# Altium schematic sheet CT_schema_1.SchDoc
size 512 x 258 mm
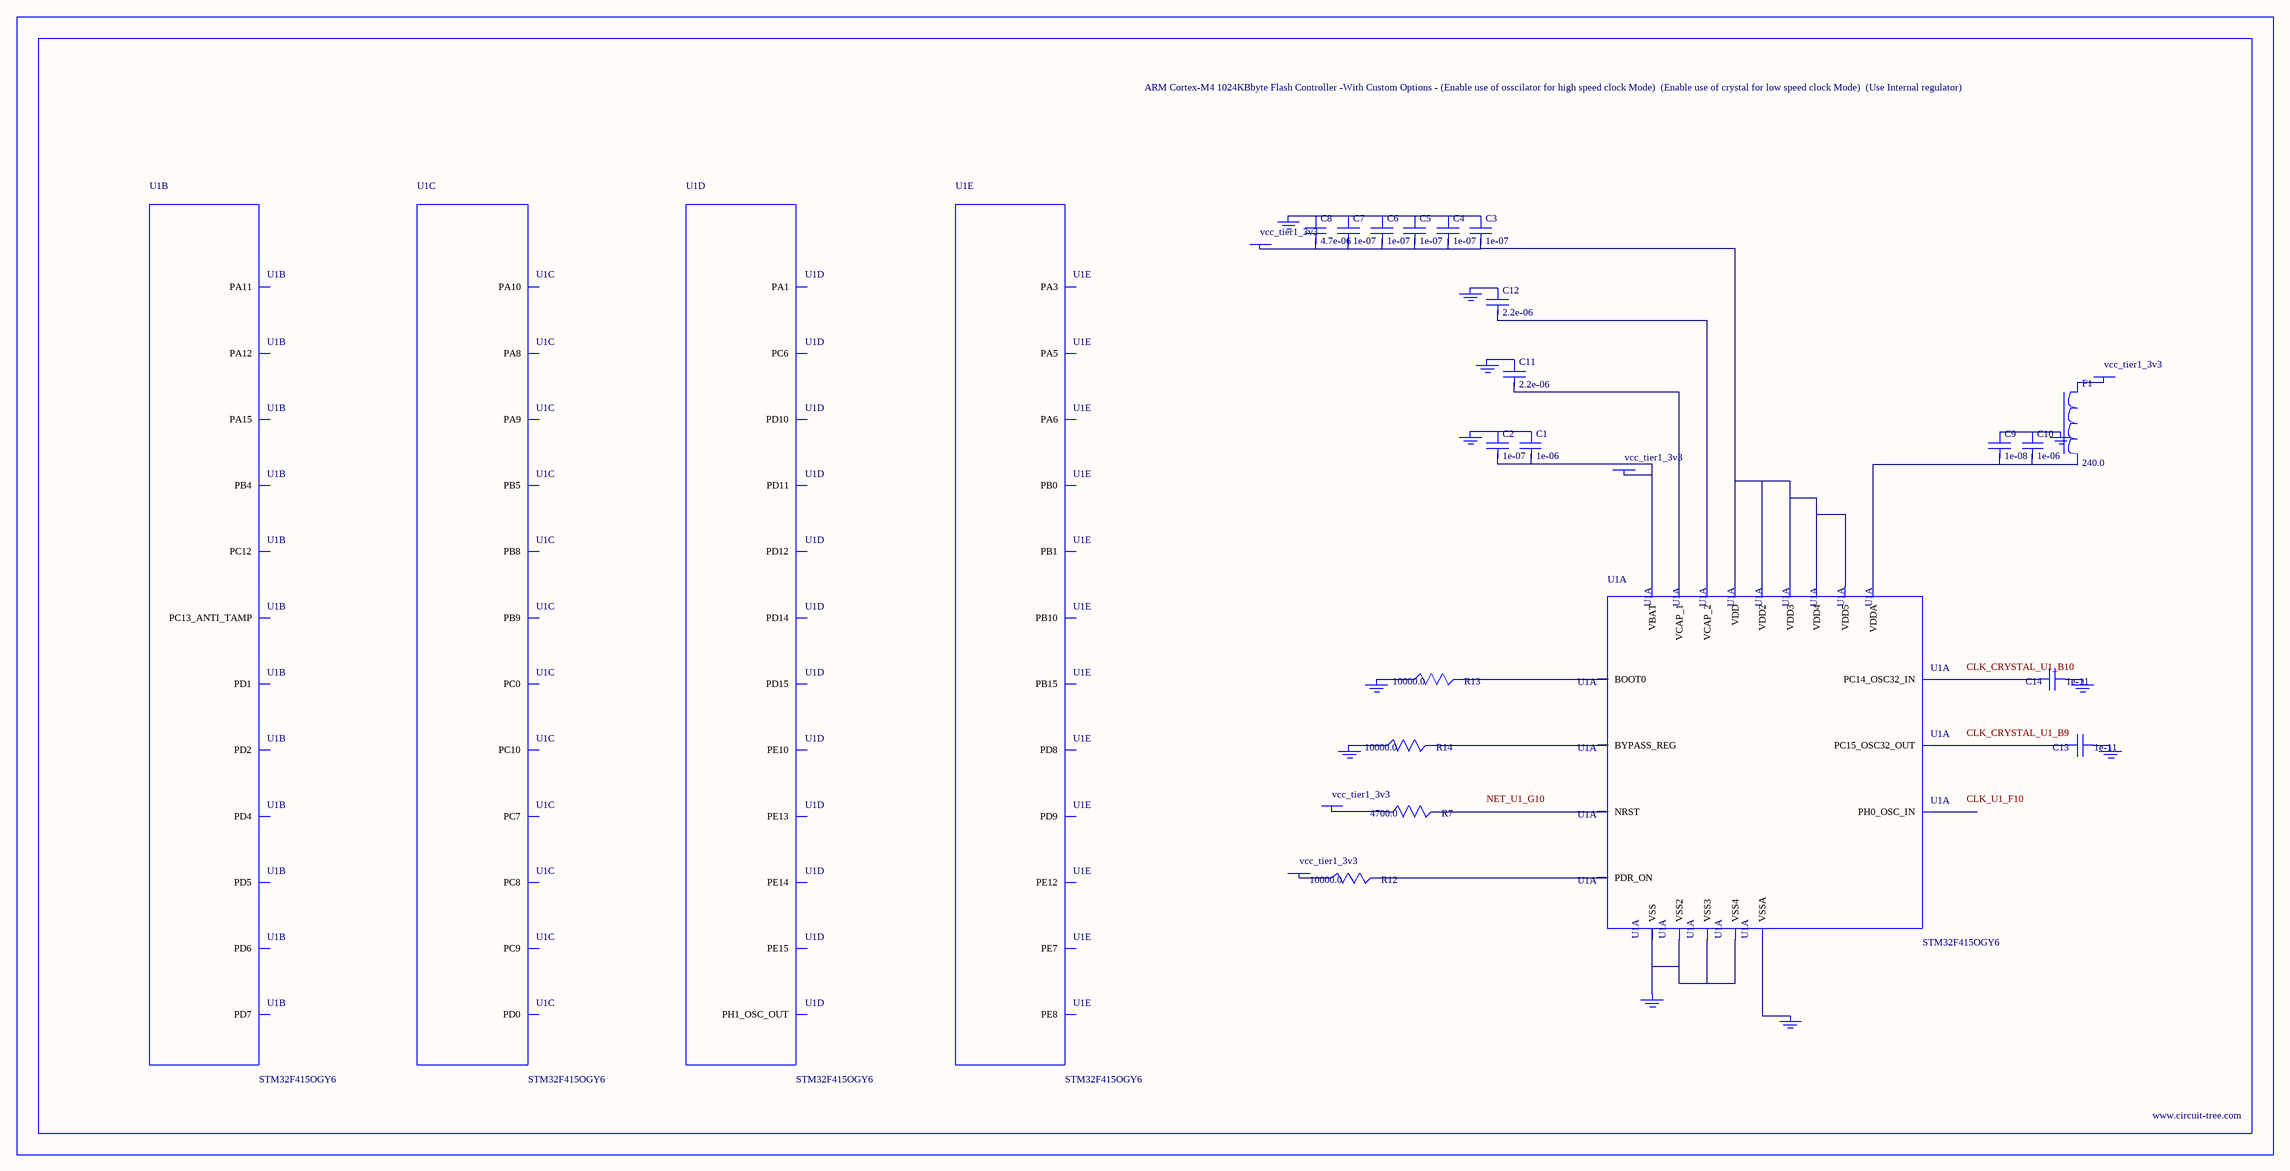
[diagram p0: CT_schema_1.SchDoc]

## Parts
BORDER0  (no value)
C1  1e-06  [C0603]
C2  1e-07  [C0603]
C3  1e-07  [C0603]
C4  1e-07  [C0603]
C5  1e-07  [C0603]
C6  1e-07  [C0603]
C7  1e-07  [C0603]
C8  4.7e-06  [C0603]
C9  1e-08  [C0603]
C10  1e-06  [C0603]
C11  2.2e-06  [C0603]
C12  2.2e-06  [C0603]
C13  1e-11  [C0402]
C14  1e-11  [C0402]
F1  240.0  [L0603]
GND_INSTANCE_0_0  (no value)
GND_INSTANCE_0_1  (no value)
GND_INSTANCE_0_2  (no value)
GND_INSTANCE_0_3  (no value)
GND_INSTANCE_0_4  (no value)
GND_INSTANCE_0_5  (no value)
GND_INSTANCE_0_6  (no value)
GND_INSTANCE_0_7  (no value)
GND_INSTANCE_0_8  (no value)
GND_INSTANCE_0_9  (no value)
GND_INSTANCE_0_10  (no value)
POWER_INSTANCE_0_0  vcc_tier1_3v3
POWER_INSTANCE_0_1  vcc_tier1_3v3
POWER_INSTANCE_0_2  vcc_tier1_3v3
POWER_INSTANCE_0_3  vcc_tier1_3v3
POWER_INSTANCE_0_4  vcc_tier1_3v3
R7  4700.0  [R0603]
R12  10000.0  [R0603]
R13  10000.0  [R0603]
R14  10000.0  [R0603]
U1  STM32F415OGY6  [WLCSP90]  (parts A,B,C,D,E of 9)

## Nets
NetC1_1: C1.1 C2.1 GND_INSTANCE_0_0.0(GND)
NetC1_2: C1.2 C2.2 POWER_INSTANCE_0_0.0(PWR) U1.A10(VBAT)
NetC3_1: C3.1 C4.1 C5.1 C6.1 C7.1 C8.1 GND_INSTANCE_0_2.0(GND)
NetC3_2: C3.2 C4.2 C5.2 C6.2 C7.2 C8.2 POWER_INSTANCE_0_2.0(PWR) U1.A1(VDD) U1.B8(VDD2) U1.E4(VDD3) U1.E6(VDD4) U1.F7(VDD5)
NetC9_1: C9.1 C10.1 GND_INSTANCE_0_1.0(GND)
NetC9_2: C9.2 C10.2 U1.G9(VDDA)
NetC11_1: C11.1 GND_INSTANCE_0_5.0(GND)
NetC11_2: C11.2 U1.F4(VCAP_1)
NetC12_1: C12.1 GND_INSTANCE_0_6.0(GND)
NetC12_2: C12.2 U1.B1(VCAP_2)
NetC13_1: C13.1 GND_INSTANCE_0_7.0(GND)
NetC13_2: C13.2 U1.B9(PC15_OSC32_OUT)
NetC14_1: C14.1 GND_INSTANCE_0_8.0(GND)
NetC14_2: C14.2 U1.B10(PC14_OSC32_IN)
NetF1_1: F1.1 POWER_INSTANCE_0_1.0(PWR)
NetGND_INSTANCE_0_3_0: GND_INSTANCE_0_3.0(GND) R13.1
NetGND_INSTANCE_0_4_0: GND_INSTANCE_0_4.0(GND) R14.1
NetGND_INSTANCE_0_9_0: GND_INSTANCE_0_9.0(GND) U1.H10(VSSA)
NetGND_INSTANCE_0_10_0: GND_INSTANCE_0_10.0(GND) U1.C9(VSS) U1.E5(VSS2) U1.E7(VSS3) U1.E8(VSS4)
NetPOWER_INSTANCE_0_3_0: POWER_INSTANCE_0_3.0(PWR) R12.1
NetPOWER_INSTANCE_0_4_0: POWER_INSTANCE_0_4.0(PWR) R7.1
NetR7_2: R7.2 U1.G10(NRST)
NetR12_2: R12.2 U1.A8(PDR_ON)
NetR13_2: R13.2 U1.A7(BOOT0)
NetR14_2: R14.2 U1.D9(BYPASS_REG)

Not connected (* = marked no-connect by the designer): F1 2; U1 A3(PC12) A4(PD4) A5(PD7) A6(PB4) A9(PC13_ANTI_TAMP) B3(PA15) B4(PD2) B5(PD6) C1(PA11) C2(PA12) C5(PD1) C6(PD5) C8(PB9) D1(PA8) D2(PA9) D3(PA10) D5(PC10) D6(PD0) D7(PB5) D8(PB8) E1(PC7) E2(PC8) E3(PC9) E10(PC0) F1(PD15) F2(PD14) F3(PC6) F5(PE14) F6(PE10) F8(PA1) F9(PH1_OSC_OUT) F10(PH0_OSC_IN) G1(PD11) G2(PD12) G3(PD10) G4(PE15) G5(PE13) G6(PE7) G7(PB0) G8(PA5) H1(PB15) H2(PD8) H3(PD9) H4(PB10) H5(PE12) H6(PE8) H7(PB1) H8(PA6) H9(PA3)

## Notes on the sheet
- Labels drawn without touching a wire or pin: CLK_CRYSTAL_U1_B9, CLK_CRYSTAL_U1_B10, CLK_U1_F10, NET_U1_G10

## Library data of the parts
BORDER0 = BORDER_PAGE0
C1 C10 = C0603C105K3RACTU
C2-C7 = 06035C104K4Z2A
C8 = GRM188R6YA475KE15D
C9 = 06035C103K4Z2A
C11 C12 = C0603C225K8RACTU
C13 C14 = C0402C100K3GACTU
F1 = Z0603C241ASMST
GND_INSTANCE_0_0-GND_INSTANCE_0_10 = GND
POWER_INSTANCE_0_0-POWER_INSTANCE_0_4 = PWR
R7 = RC0603JR-074K7L
R12-R14 = RC0603JR-0710KL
